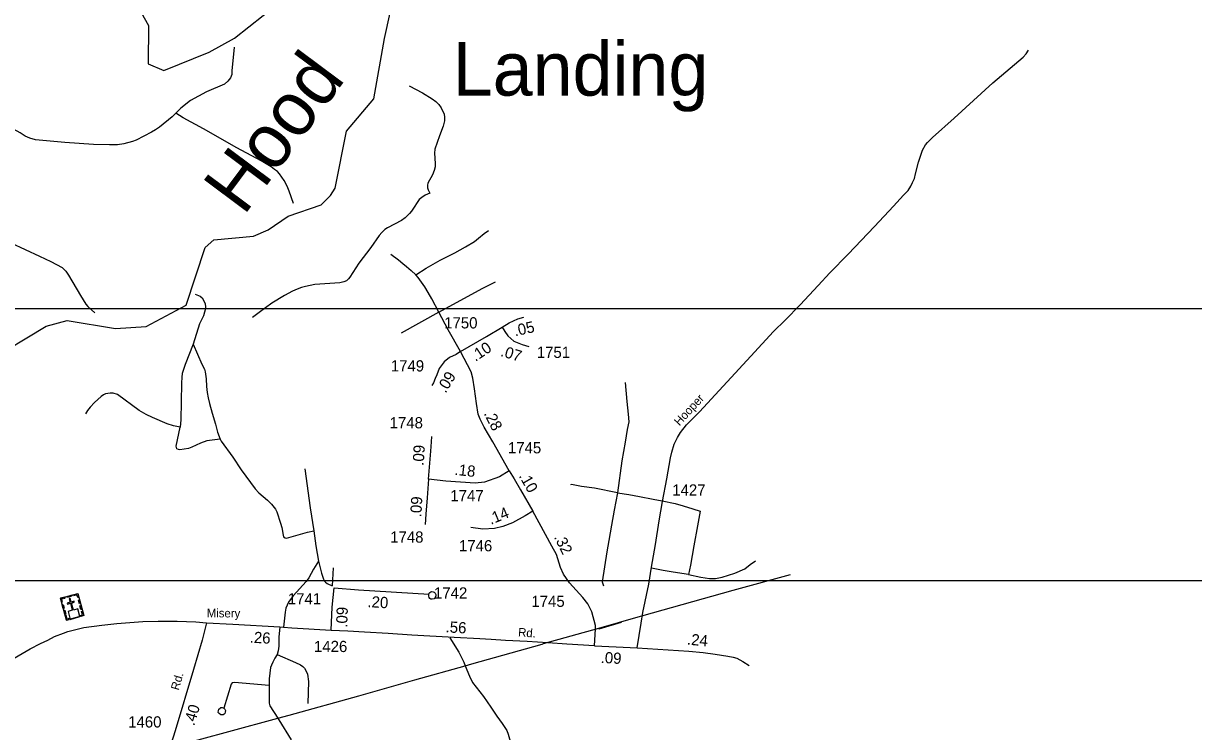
# Model space of a CAD drawing. Extents: x 2225501 to 2309677, y 165449 to 227696.
# Drawn here: x 2267922 to 2280990, y 204979 to 212881 of the extents above; entities that cross this region are included whole.
import ezdxf

# ---------------------------------------------------------------- set-up
doc = ezdxf.new("R2010")
doc.units = 0
for name, color, linetype in [('Black Area Fill Shapes', 7, 'Continuous'), ('E_RDY_CMT_EOP', 7, 'Continuous'), ('MARK ENDS WORD SYMBOL CELL', 7, 'Continuous'), ('Old_Level_3', 7, 'Continuous'), ('Old_Level_33', 7, 'Continuous'), ('P_HYD_Endwall_838_01_48_Dia_Single-Top_CELL', 7, 'Continuous'), ('P_HYD_Pipe_Pipe_Removal', 7, 'Continuous'), ('P_HYD_Typical_Terminator_CELL', 7, 'Continuous'), ('P_RDY_Concrete_Monolithic_Island', 7, 'Continuous'), ('P_RDY_Dimension_Text', 7, 'Continuous'), ('Prop Support', 7, 'Continuous'), ('Scratch_Level_1', 7, 'Continuous'), ('Typical Terminator CELL', 7, 'Continuous')]:
    doc.layers.add(name, color=color, linetype=linetype)

msp = doc.modelspace()

# ---------------------------------------------------------------- linework, layer by layer
at = {"layer": 'Black Area Fill Shapes'}
for points in [[(2274829, 206270), (2275850, 206557), (2276488, 206733)], [(2274348, 206134), (2274788, 206258), (2274829, 206270)], [(2273714, 205955), (2273731, 205960), (2274348, 206134)], [(2272857, 205714), (2272930, 205735), (2273714, 205955)], [(2270764, 205129), (2270889, 205163), (2271666, 205378), (2272294, 205555), (2272857, 205714)], [(2269612, 204815), (2270217, 204979), (2270764, 205129)]]:
    msp.add_lwpolyline(points, dxfattribs=at)
at = {"layer": 'Old_Level_3'}
for p, q in [((2272563, 209658), (2272139, 209423)), ((2271380, 206807), (2271369, 206606)), ((2274598, 206195), (2274348, 206123)), ((2274348, 206134), (2274348, 206123))]:
    msp.add_line(p, q, dxfattribs=at)
for points in [[(2270277, 212615), (2270250, 212351), (2270248, 212312), (2270243, 212292), (2270233, 212272), (2270205, 212238), (2270168, 212204), (2269966, 212118), (2269788, 212019), (2269681, 211936), (2269623, 211879)], [(2272230, 212183), (2272380, 212107), (2272488, 212040), (2272526, 212010), (2272560, 211976), (2272587, 211937), (2272620, 211868), (2272626, 211834), (2272624, 211794), (2272608, 211734), (2272567, 211625), (2272516, 211476), (2272511, 211433), (2272521, 211316), (2272521, 211280), (2272509, 211238), (2272490, 211192), (2272439, 211099), (2272434, 211075), (2272436, 211047), (2272442, 211025), (2272461, 210988)], [(2269623, 211879), (2269585, 211839), (2269442, 211724), (2269398, 211694), (2269354, 211667), (2269181, 211579), (2269140, 211563), (2269044, 211536), (2268973, 211526), (2268882, 211524), (2268706, 211529), (2268384, 211551), (2268057, 211583), (2267993, 211601), (2267941, 211624), (2267884, 211659), (2267776, 211720), (2267663, 211791), (2267554, 211847)], [(2270938, 210873), (2270890, 211010), (2270867, 211066), (2270833, 211129), (2270782, 211203), (2270758, 211229), (2270727, 211252), (2270687, 211282), (2270578, 211346), (2270304, 211493), (2269932, 211705), (2269706, 211826), (2269623, 211879)], [(2267227, 210939), (2267300, 210872), (2267449, 210764), (2267515, 210703), (2267535, 210675), (2267613, 210514), (2267639, 210496), (2267687, 210471), (2267781, 210432), (2268103, 210284), (2268228, 210224), (2268355, 210157), (2268396, 210116), (2268425, 210072), (2268559, 209846), (2268620, 209748), (2268642, 209723), (2268719, 209652)], [(2272461, 210988), (2272409, 210963), (2272371, 210940), (2272343, 210916), (2272318, 210882), (2272287, 210830), (2272257, 210787), (2272233, 210759), (2272184, 210712), (2272144, 210682), (2271988, 210598), (2271958, 210580), (2271924, 210547), (2271894, 210513), (2271800, 210380), (2271666, 210204), (2271566, 210049), (2271552, 210030), (2271529, 210010), (2271499, 209996), (2271457, 209987), (2271175, 209966), (2271072, 209945), (2271026, 209932), (2270980, 209915), (2270928, 209893), (2270839, 209845), (2270696, 209758), (2270553, 209656), (2270482, 209599)], [(2272304, 210075), (2272419, 210149), (2272577, 210238), (2272739, 210322), (2272860, 210389), (2272959, 210449), (2273006, 210483), (2273068, 210535), (2273115, 210570)], [(2272024, 210305), (2272111, 210243), (2272160, 210203), (2272202, 210169), (2272252, 210124), (2272304, 210075)], [(2272563, 209658), (2272483, 209807), (2272443, 209879), (2272406, 209941), (2272369, 209995), (2272331, 210045), (2272304, 210075)], [(2272563, 209658), (2272719, 209743), (2273054, 209926), (2273195, 209998)], [(2269841, 209861), (2269895, 209838), (2269919, 209817), (2269938, 209786), (2269950, 209753), (2269956, 209719), (2269953, 209685), (2269945, 209657), (2269932, 209619), (2269887, 209530), (2269818, 209303)], [(2272802, 209218), (2272665, 209463), (2272563, 209658)], [(2269818, 209303), (2269729, 209075), (2269695, 208976), (2269690, 208935), (2269688, 208867), (2269683, 208658), (2269681, 208459), (2269671, 208374)], [(2269818, 209303), (2269916, 209078), (2269943, 209023), (2269953, 208993), (2269962, 208913), (2269967, 208829), (2269974, 208763), (2269985, 208704), (2270000, 208641), (2270029, 208532), (2270066, 208409), (2270090, 208321), (2270119, 208241)], [(2274643, 208875), (2274660, 208660), (2274677, 208519), (2274683, 208434), (2274666, 208349), (2274643, 208208), (2274604, 207999), (2274557, 207642)], [(2269671, 208374), (2269597, 208391), (2269528, 208412), (2269364, 208482), (2269294, 208517), (2269216, 208562), (2268973, 208739), (2268926, 208754), (2268891, 208755), (2268838, 208746), (2268817, 208737), (2268789, 208717), (2268714, 208652), (2268666, 208599), (2268639, 208563), (2268615, 208526)], [(2270119, 208241), (2269969, 208221), (2269901, 208198), (2269802, 208151), (2269764, 208139), (2269668, 208123), (2269654, 208125), (2269636, 208135), (2269630, 208150), (2269629, 208163), (2269671, 208374)], [(2270119, 208241), (2270131, 208219), (2270259, 208039), (2270353, 207900), (2270509, 207686), (2270550, 207643), (2270647, 207562), (2270692, 207516), (2270737, 207462), (2270751, 207431), (2270794, 207305), (2270807, 207257), (2270822, 207169), (2270828, 207152), (2270844, 207140), (2270859, 207138), (2271094, 207205), (2271167, 207218)], [(2271063, 207911), (2271126, 207477), (2271167, 207218)], [(2274557, 207642), (2274300, 207693), (2274156, 207715), (2274043, 207735), (2274033, 207733)], [(2274557, 207642), (2274518, 207449), (2274489, 207281), (2274458, 207110), (2274437, 206983), (2274386, 206649), (2274402, 206604)], [(2274557, 207642), (2274682, 207623), (2274801, 207601), (2274954, 207573), (2275056, 207553)], [(2275056, 207553), (2275201, 207523), (2275291, 207497), (2275397, 207463), (2275479, 207439)], [(2275479, 207439), (2275451, 207273), (2275410, 207053), (2275371, 206834), (2275349, 206733)], [(2271167, 207218), (2271189, 207052), (2271218, 206879)], [(2271218, 206879), (2271162, 206792), (2271108, 206695), (2271078, 206653), (2270936, 206495), (2270911, 206465), (2270883, 206422), (2270866, 206388), (2270853, 206354), (2270844, 206312), (2270827, 206144)], [(2271218, 206879), (2271252, 206748), (2271270, 206689), (2271282, 206661), (2271294, 206644), (2271313, 206630), (2271369, 206606)], [(2275349, 206733), (2275486, 206702), (2275585, 206688), (2275650, 206688), (2275724, 206702), (2275866, 206747), (2275980, 206795), (2276040, 206844), (2276097, 206885)], [(2275349, 206733), (2275177, 206758), (2275066, 206776), (2274935, 206803)], [(2272449, 206504), (2272454, 206524), (2272462, 206532), (2272473, 206539), (2272483, 206541), (2272497, 206539), (2272509, 206535), (2272520, 206524), (2272526, 206509), (2272527, 206494), (2272522, 206476), (2272510, 206461), (2272488, 206455), (2272472, 206457), (2272462, 206462), (2272452, 206475), (2272448, 206490), (2272449, 206504)], [(2270785, 206147), (2270776, 206033), (2270773, 205931), (2270766, 205879), (2270756, 205839)], [(2272684, 206025), (2272786, 205864), (2272808, 205820), (2272841, 205753), (2272857, 205714)], [(2270756, 205839), (2270731, 205799), (2270707, 205754), (2270692, 205720), (2270682, 205692), (2270673, 205632), (2270668, 205566), (2270667, 205494)], [(2270756, 205839), (2270959, 205751), (2271016, 205722), (2271042, 205703), (2271060, 205685), (2271085, 205645), (2271096, 205620), (2271106, 205539), (2271099, 205293)], [(2272857, 205714), (2272903, 205595), (2272936, 205526), (2273060, 205369), (2273142, 205252), (2273209, 205149), (2273268, 205068), (2273319, 204992), (2273335, 204949), (2273423, 204654), (2273509, 204449), (2273522, 204405), (2273529, 204367), (2273529, 204325), (2273513, 204177)], [(2270667, 205494), (2270280, 205527), (2270253, 205524), (2270241, 205508), (2270160, 205240)], [(2270667, 205494), (2270665, 205294), (2270673, 205266), (2270764, 205129)], [(2270160, 205240), (2270172, 205227), (2270178, 205212), (2270176, 205195), (2270171, 205180), (2270163, 205172), (2270151, 205165), (2270125, 205165), (2270107, 205179), (2270098, 205193), (2270100, 205215), (2270104, 205227), (2270120, 205241), (2270128, 205246), (2270143, 205246), (2270160, 205240)], [(2270764, 205129), (2270775, 205111), (2270911, 204888)]]:
    msp.add_lwpolyline(points, dxfattribs=at)
at = {"layer": 'Old_Level_33'}
for points in [[(2274775, 205912), (2274821, 206188), (2274841, 206308), (2274906, 206622), (2274937, 206813), (2274982, 207065), (2275023, 207329), (2275060, 207546), (2275109, 207797), (2275150, 208032), (2275164, 208097), (2275189, 208187), (2275226, 208259), (2275262, 208315), (2275328, 208402), (2275473, 208547), (2276047, 209168), (2276299, 209442), (2276428, 209568), (2276595, 209739), (2276798, 209955), (2276929, 210097), (2277134, 210307), (2277428, 210614), (2277639, 210840), (2277751, 210965), (2277801, 211017), (2277832, 211063), (2277852, 211106), (2277872, 211150), (2277885, 211202), (2277918, 211333), (2277943, 211410), (2277963, 211465), (2277995, 211524), (2278019, 211552), (2278073, 211606), (2278318, 211824), (2278747, 212216), (2279088, 212505), (2279120, 212541), (2279147, 212582)], [(2272802, 209218), (2273095, 209387), (2273269, 209493)], [(2273269, 209493), (2273348, 209540), (2273442, 209584), (2273511, 209602)], [(2273269, 209493), (2273299, 209443), (2273331, 209395), (2273398, 209334), (2273492, 209297), (2273566, 209275)], [(2272802, 209218), (2272753, 209187), (2272680, 209153), (2272620, 209106), (2272566, 209029), (2272539, 208960), (2272521, 208920), (2272502, 208871), (2272484, 208839)], [(2273347, 207888), (2273165, 208210), (2273066, 208376), (2273021, 208465), (2273002, 208522), (2272982, 208638), (2272958, 208802), (2272941, 208923), (2272924, 208992), (2272802, 209218)], [(2272446, 207796), (2272471, 208108), (2272478, 208210), (2272483, 208270)], [(2272446, 207796), (2272431, 207588), (2272416, 207405), (2272409, 207288)], [(2273347, 207888), (2273238, 207823), (2273072, 207761), (2272966, 207749), (2272641, 207774), (2272446, 207796)], [(2273347, 207888), (2273401, 207799), (2273473, 207675), (2273612, 207437)], [(2273612, 207437), (2273525, 207385), (2273384, 207306), (2273275, 207266), (2273183, 207244), (2273052, 207239), (2272917, 207254)], [(2274301, 205937), (2274310, 206125), (2274310, 206164), (2274270, 206316), (2274227, 206405), (2274171, 206475), (2274020, 206640), (2273955, 206735), (2273919, 206808), (2273876, 206953), (2273823, 207049), (2273612, 207437)], [(2271360, 206110), (2271369, 206366), (2271394, 206581)], [(2271394, 206581), (2271664, 206561), (2272455, 206513)], [(2267819, 205797), (2267998, 205902), (2268112, 205962), (2268193, 206000), (2268270, 206038), (2268370, 206075), (2268419, 206094), (2268597, 206139), (2268796, 206167), (2268966, 206184), (2269255, 206207), (2269428, 206212), (2269526, 206212), (2269639, 206209), (2269847, 206204), (2269967, 206192)], [(2269967, 206192), (2269918, 206000), (2269823, 205673), (2269618, 204987), (2269528, 204705), (2269492, 204567), (2269464, 204402), (2269445, 204266), (2269434, 204162)], [(2269967, 206192), (2270261, 206177), (2270785, 206147), (2270827, 206144), (2270921, 206137), (2271360, 206110)], [(2271360, 206110), (2271546, 206103), (2271730, 206093), (2271995, 206075), (2272261, 206058), (2272732, 206031), (2273020, 206019), (2273145, 206011), (2273306, 205999), (2273548, 205986), (2273780, 205973), (2273989, 205958), (2274298, 205938), (2274301, 205937)], [(2274301, 205937), (2274541, 205924), (2274775, 205912)], [(2274775, 205912), (2275352, 205876), (2275512, 205861), (2275646, 205843), (2275788, 205821), (2275849, 205808), (2275889, 205796), (2275923, 205780), (2275957, 205761), (2276028, 205715)]]:
    msp.add_lwpolyline(points, dxfattribs=at)
at = {"layer": 'P_HYD_Endwall_838_01_48_Dia_Single-Top_CELL'}
for points in [[(2268336, 206466), (2268528, 206518), (2268595, 206272), (2268403, 206220)], [(2268407, 206485), (2268457, 206499), (2268460, 206488), (2268410, 206474)], [(2268539, 206476), (2268528, 206473), (2268520, 206504), (2268481, 206494), (2268478, 206504), (2268528, 206518)], [(2268347, 206424), (2268358, 206427), (2268349, 206458), (2268389, 206469), (2268386, 206479), (2268336, 206466)], [(2268366, 206352), (2268355, 206394), (2268366, 206397), (2268377, 206355)], [(2268444, 206231), (2268552, 206261), (2268528, 206348), (2268480, 206335), (2268458, 206413), (2268490, 206422), (2268487, 206433), (2268455, 206424), (2268444, 206465), (2268433, 206462), (2268444, 206421), (2268412, 206412), (2268415, 206402), (2268447, 206410), (2268468, 206332), (2268420, 206319)], [(2268547, 206403), (2268536, 206444), (2268547, 206447), (2268558, 206406)], [(2268565, 206339), (2268553, 206381), (2268564, 206384), (2268576, 206342)], [(2268384, 206287), (2268373, 206329), (2268384, 206332), (2268395, 206290)], [(2268434, 206229), (2268431, 206240), (2268410, 206234), (2268400, 206273), (2268389, 206270), (2268402, 206220)], [(2268563, 206264), (2268560, 206275), (2268581, 206280), (2268570, 206319), (2268581, 206322), (2268595, 206272)]]:
    msp.add_lwpolyline(points, close=True, dxfattribs=at)
at = {"layer": 'P_HYD_Pipe_Pipe_Removal'}
msp.add_lwpolyline([(2266254, 165449), (2309677, 165449), (2309677, 209697), (2266254, 209697)], close=True, dxfattribs=at)
at = {"layer": 'P_HYD_Typical_Terminator_CELL'}
msp.add_line((2244657, 206666), (2298327, 206666), dxfattribs=at)
at = {"layer": 'Prop Support'}
msp.add_lwpolyline([(2268575, 214107), (2268668, 213892), (2268955, 213509), (2269320, 212856), (2269315, 212430), (2269491, 212357), (2269997, 212561), (2270279, 212716), (2270601, 212969), (2270825, 213096), (2271274, 213176), (2271765, 213202), (2271981, 213263), (2272073, 213255)], dxfattribs=at)
at = {"layer": 'Typical Terminator CELL'}
msp.add_lwpolyline([(2266822, 208260), (2266946, 208343), (2267177, 208588), (2267349, 208922), (2267506, 209100), (2268176, 209503), (2268409, 209564), (2268951, 209478), (2269293, 209498), (2269740, 209735), (2269951, 210381), (2270050, 210464), (2270491, 210508), (2270657, 210577), (2270880, 210730), (2271246, 210857), (2271353, 210960), (2271402, 211044), (2271530, 211678), (2271835, 212040), (2271953, 212713), (2272073, 213255)], dxfattribs=at)

# ---------------------------------------------------------------- texts
at = {"layer": 'E_RDY_CMT_EOP'}
for s, p in [('1750', (2272621, 209477)), ('1751', (2273655, 209148)), ('1749', (2272025, 208997)), ('1748', (2272012, 208362)), ('1745', (2273333, 208083)), ('1747', (2272690, 207549)), ('1427', (2275168, 207612)), ('1748', (2272018, 207087)), ('1746', (2272786, 206990)), ('1741', (2270875, 206398)), ('1742', (2272507, 206463)), ('1745', (2273595, 206370)), ('1426', (2271167, 205866)), ('1460', (2269092, 205024))]:
    msp.add_text(s, height=125, dxfattribs=at).set_placement(p)
at = {"layer": 'MARK ENDS WORD SYMBOL CELL'}
for s, rotation, p in [('Hooper', 47.232, (2275248, 208384)), ('Misery', 359.336, (2269969, 206255)), ('Rd.', 355.6287, (2273444, 206042)), ('Rd.', 74.0575, (2269657, 205433))]:
    msp.add_text(s, height=95, rotation=rotation, dxfattribs=at).set_placement(p)
at = {"layer": 'P_RDY_Concrete_Monolithic_Island'}
msp.add_text('Landing', height=600, dxfattribs=at).set_placement((2272716, 212075))
at = {"layer": 'P_RDY_Dimension_Text'}
for s, rotation, p in [('.05', 12.6873, (2273413, 209388)), ('.10', 33.7897, (2272970, 209103)), ('.07', 342.7913, (2273242, 209172)), ('.09', 58.7668, (2272637, 208748)), ('.28', 297.0429, (2273060, 208529)), ('.09', 86.5907, (2272392, 207942)), ('.18', 353.6562, (2272732, 207844)), ('.10', 299.6528, (2273451, 207832)), ('.09', 86.7623, (2272365, 207367)), ('.14', 22.3916, (2273142, 207285)), ('.32', 296.5516, (2273844, 207149)), ('.20', 356.4899, (2271761, 206368)), ('.09', 88.1292, (2271538, 206136)), ('.26', 356.7822, (2270447, 205971)), ('.56', 356.7514, (2272634, 206086)), ('.24', 354.9064, (2275329, 205949)), ('.09', 356.8405, (2274366, 205745)), ('.40', 73.3621, (2269829, 205036))]:
    msp.add_text(s, height=125, rotation=rotation, dxfattribs=at).set_placement(p)
at = {"layer": 'Scratch_Level_1'}
msp.add_text('Hood', height=600, rotation=53.3006, dxfattribs=at).set_placement((2270381, 210724))

doc.saveas('drawing.dxf')
